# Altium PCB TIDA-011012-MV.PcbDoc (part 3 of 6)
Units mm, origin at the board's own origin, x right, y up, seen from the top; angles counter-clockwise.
Board outline 360 x 280 mm, 4 copper layers (Top Layer, Layer 1, Layer 2, Bottom Layer), stack 2.066 mm thick; 566 components, 345 nets, 1738 pads, 2486 vias.
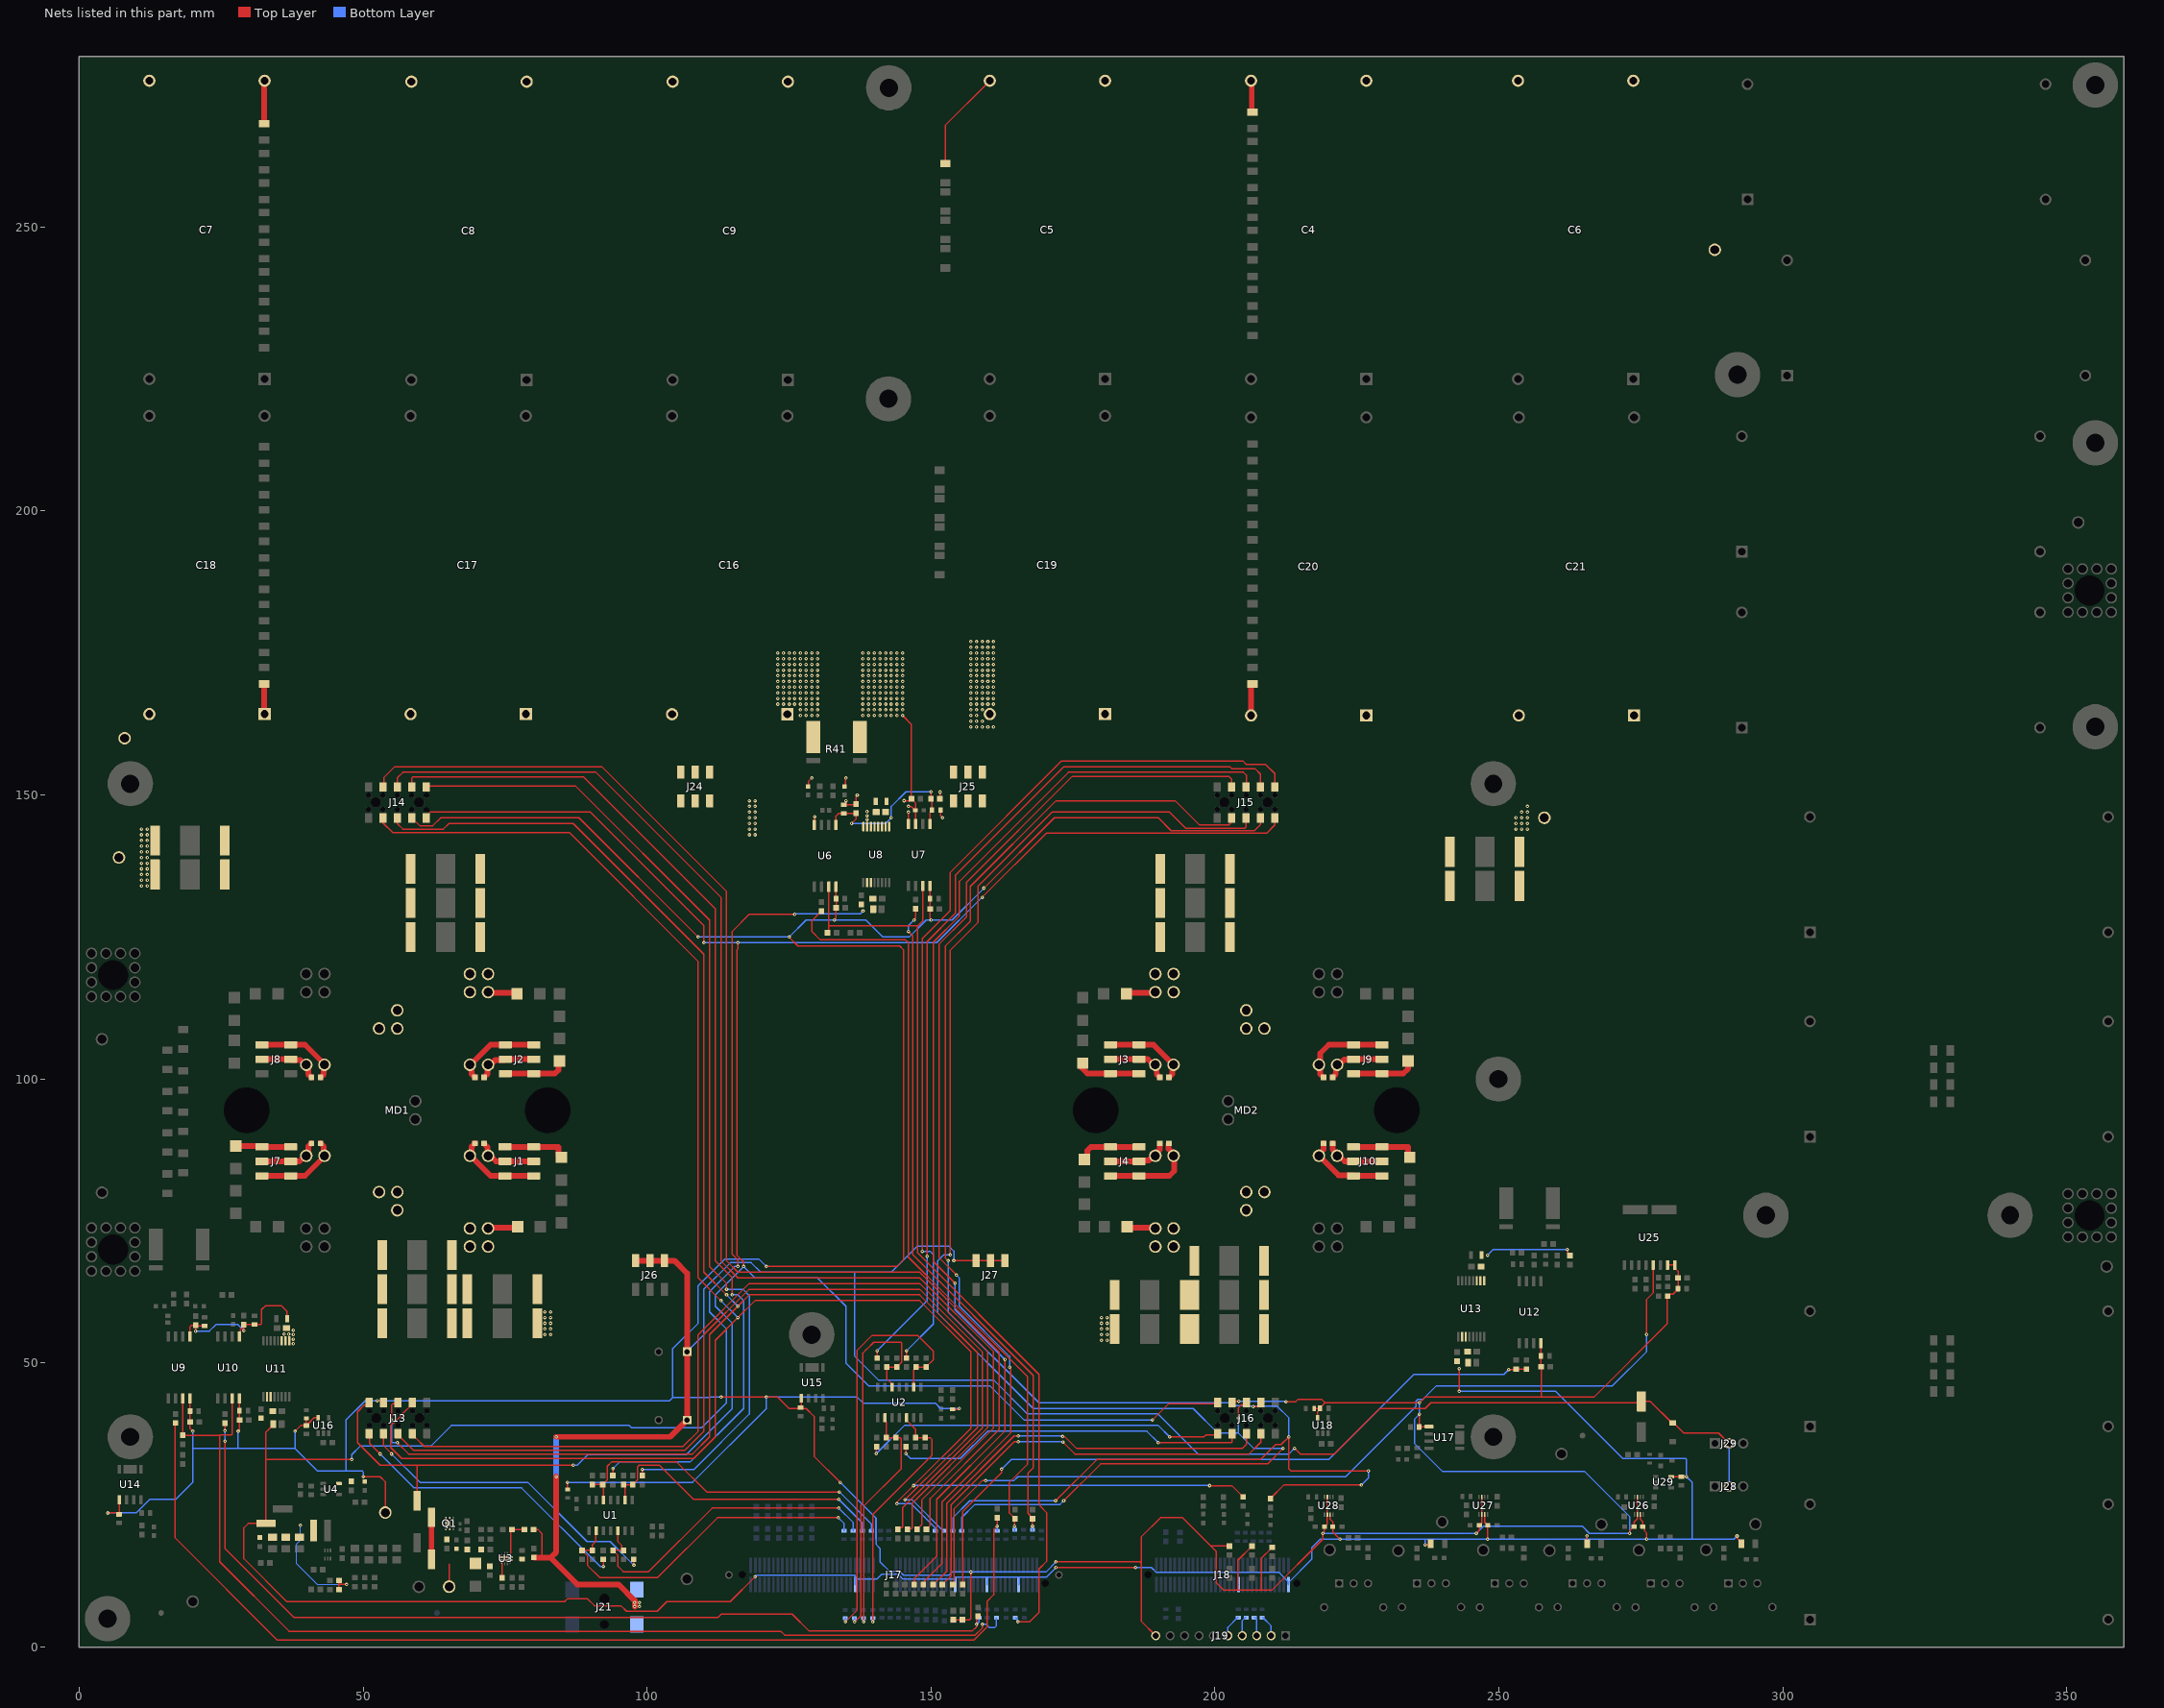
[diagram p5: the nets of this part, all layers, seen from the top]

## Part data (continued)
R142: library part CMP-0022816-5, "RES, 15.0 k, 1%, 0.1 W, 0603", Manufacturer=Yageo, Power_W=100mW, Supplier Part Number 1=311-15.0KHRCT-ND, TempCo="100 ppm/C", Tolerance_%=1%, Value2=0.1W, Value_Code=15k0, ValueDisplayed=15.0k
R144: library part CMP-0022917-4, "RES, 220 k, 1%, 0.1 W, 0603", Manufacturer=Yageo, Power_W=100mW, Supplier Part Number 1=311-220KHRCT-ND, TempCo="100 ppm/C", Tolerance_%=1%, Value2=0.1W, Value_Code=220k
R145: library part CMP-0023404-3, "RES, 10.0 k, 0.1%, 0.1 W, 0603", Manufacturer="Susumu Co Ltd", Power_W=100mW, Supplier Part Number 1=RG16P10.0KBCT-ND, TempCo="25 ppm/C", Tolerance_%=0.1%, Value2=0.1W, Value_Code=10k0, ValueDisplayed=10.0k
R146: library part CMP-0023020-5, "RES, 30.0 k, 1%, 0.1 W, 0603", Manufacturer=Yageo, Power_W=100mW, Supplier Part Number 1=311-30.0KHRCT-ND, TempCo="100 ppm/C", Tolerance_%=1%, Value2=0.1W, Value_Code=30k0, ValueDisplayed=30.0k
R151 R152 R166 R167 R181 R182: library part CMP-0025687-2, "RES, 10.0, 0.1%, 0.1 W, 0603", Manufacturer=Vishay-Dale, Power_W=100mW, Supplier Part Number 1=TNP10.0AACT-ND, TempCo="25 ppm/C", Tolerance_%=0.1%, Value2=0.1W, Value_Code=10R0, ValueDisplayed=10.0
R153 R163 R168 R178 R183: library part CMP-0023099-5, "RES, 40.2, 1%, 0.1 W, 0603", Manufacturer=Yageo, Power_W=100mW, Supplier Part Number 1=311-40.2HRCT-ND, TempCo="100 ppm/C", Tolerance_%=1%, Value2=0.1W, Value_Code=40R2, ValueDisplayed=40.2
R154 R169: library part CMP-0022736-4, "RES, 100, 1%, 0.1 W, 0603", Manufacturer=Yageo, Power_W=100mW, Supplier Part Number 1=311-100HRCT-ND, TempCo="100 ppm/C", Tolerance_%=1%, Value2=0.1W, Value_Code=100R, ValueDisplayed=100
R155 R156 R157 R158 R159 R160 R161 R162 R170 R171 R172 R173 R174 R175 R176 R177: library part CMP-0120473-1, "Thick Film High Voltage Chip Resistors 1206 1.5MOhm ±1% ±100ppm/°C", Manufacturer=Bourns, Operating Temperature Range="-55°C to +155°C", Power_W=250mW, TempCo=100ppm/°C, Tolerance_%=1%
R164 R179: library part CMP-0023153-5, "RES, 4.70 k, 1%, 0.1 W, 0603", Manufacturer=Yageo, Power_W=100mW, Supplier Part Number 1=311-4.70KHRCT-ND, TempCo="100 ppm/C", Tolerance_%=1%, Value2=0.1W, Value_Code=4k70, ValueDisplayed=4.70k
R165 R180 R185: library part CMP-0025892-5, "RES, 18 k, 5%, 0.1 W, 0603", Manufacturer=Yageo, Power_W=100mW, Supplier Part Number 1=311-18KGRCT-ND, TempCo="100 ppm/C", Tolerance_%=5%, Value2=0.1W, Value_Code=18k0, ValueDisplayed=18k
R184: library part CMP-0022680-4, "RES, 1.00 k, 1%, 0.1 W, 0603", Manufacturer=Panasonic, Power_W=100mW, Supplier Part Number 1=P1.00KHCT-ND, TempCo="100 ppm/C", Tolerance_%=1%, Value2=0.1W, Value_Code=1k00, ValueDisplayed=1.00k
R187: library part CMP-0023921-2, "RES, 200, 0.1%, 0.1 W, 0603", Manufacturer="Yageo America", Power_W=100mW, TempCo="25 ppm/C", Tolerance_%=0.1%, Value2=0.1W, Value_Code=200R, ValueDisplayed=200
R188: library part CMP-0098286-1, "10 kOhms ±5% 0.1W, 1/10W Chip Resistor 0603 (1608 Metric) Thick Film", Digikey Part Number=541-CRCW060310K0JNEBCCT-ND, Manufacturer=Vishay, Mouser Part Number=71-CRCW060310K0JNEBC, Operating Temperature Range="-55°C to +155°C", Power_W=100mW, TempCo=200ppm/°C, Tolerance_%=5%
R190 R192: library part CMP-0023235-5, "RES, 680, 1%, 0.1 W, 0603", Manufacturer=Yageo, Power_W=100mW, Supplier Part Number 1=311-680HRCT-ND, TempCo="100 ppm/C", Tolerance_%=1%, Value2=0.1W, Value_Code=680R, ValueDisplayed=680
R193 R196 R208: library part CMP-0023069-5, "RES, 390, 1%, 0.1 W, 0603", Manufacturer=Yageo, Power_W=100mW, Supplier Part Number 1=311-390HRCT-ND, TempCo="100 ppm/C", Tolerance_%=1%, Value2=0.1W, Value_Code=390R, ValueDisplayed=390
R194 R197 R209: library part CMP-0022769-5, "RES, 120, 1%, 0.1 W, 0603", Manufacturer=Yageo, Power_W=100mW, Supplier Part Number 1=311-120HRCT-ND, TempCo="100 ppm/C", Tolerance_%=1%, Value2=0.1W, Value_Code=120R, ValueDisplayed=120
R195 R198 R210: library part CMP-0025815-4, "RES, 47, 5%, 0.1 W, AEC-Q200 Grade 0, 0603", Manufacturer=Vishay-Dale, Power_W=100mW, Supplier Part Number 1=541-47GCT-ND, TempCo="200 ppm/C", Tolerance_%=5%, Value2=0.1W, Value_Code=47R0, ValueDisplayed=47
R199: library part CMP-0022553-4, "RES, 68.1, 1%, 0.1 W, AEC-Q200 Grade 0, 0603", Manufacturer=Vishay-Dale, Power_W=100mW, Supplier Part Number 1=541-68.1HCT-ND, TempCo="100 ppm/C", Tolerance_%=1%, Value2=0.1W, Value_Code=68R1, ValueDisplayed=68.1
R200 R201 R206 R207 R211 R212 R213 R214: library part CMP-0018693-3, "RES, 4.7, 5%, 0.25 W, AEC-Q200 Grade 0, 1206", Manufacturer=Vishay-Dale, Power_W=250mW, Supplier Part Number 1=541-4.7ECT-ND, TempCo="200 ppm/C", Tolerance_%=5%, Value2=0.25W, Value_Code=4R70, ValueDisplayed=4.7
R202: library part CMP-0025942-5, "RES, 8.2 k, 5%, 0.1 W, 0603", Manufacturer=Yageo, Power_W=100mW, Supplier Part Number 1=311-8.2KGRCT-ND, TempCo="100 ppm/C", Tolerance_%=5%, Value2=0.1W, Value_Code=8k20, ValueDisplayed=8.2k
R203: library part CMP-0025894-5, "RES, 1.2 k, 5%, 0.1 W, 0603", Manufacturer=Yageo, Power_W=100mW, Supplier Part Number 1=311-1.2KGRCT-ND, TempCo="100 ppm/C", Tolerance_%=5%, Value2=0.1W, Value_Code=1k20, ValueDisplayed=1.2k
TP1 TP3 TP13 TP14: library part CMP-0055147-2, "Test Point, Multipurpose, Red, TH", Color=Red, Manufacturer="Keystone Electronics", Supplier Part Number 1=36-5010-ND
TP2 TP17 TP18 TP21 TP22 TP23: library part CMP-0055148-2, "Test Point, Multipurpose, Black, TH", Color=Black, Manufacturer="Keystone Electronics", Supplier Part Number 1=36-5011-ND
TP4 TP5 TP6 TP7 TP8 TP9 TP10 TP11 TP12 TP15 TP16 TP19 TP20: library part CMP-0055155-2, "Test Point, Compact, Blue, TH", Color=Blue, Manufacturer="Keystone Electronics", Supplier Part Number 1=36-5122-ND
U1 U2: library part CMP-0093039-1, "Schmitt-trigger inputs quadruple bus buffer gates with 3-state outputs 14-SOIC -40 to 125", Manufacturer="Texas Instruments", Max Supply Voltage=6V, Min Supply Voltage=2V, Mouser Part Number=595-SN74HCS126DR, Nominal Supply Current=0.1uA, Operating Temperature Range="-40°C to +125°C"
U3: library part CMP-0088329-1, "2.7- 23V, 5.5 A, 28 mΩ Reverse Current Blocking eFuse with Input Reverse Polarity Protection", Manufacturer="Texas Instruments", Max Supply Voltage=23V, Min Supply Voltage=2.7V, Nominal Supply Current=0.5-6A, Operating Temperature Range="-40°C to +125°C", Output Voltage=42V, Threshold Voltage=1.2/1.1V
U4: library part CMP-0074640-3, "500-mA, Low IQ, Small Size, Low Dropout Regulator, DBV0005A (SOT-23-5)", Alternate Manufacturer="Texas Instruments"
U5: library part CMP-0047826-1, "4.2-V to 17-V Input, 3-A Synchronous Buck Converter in SOT563", Manufacturer="Texas Instruments", Max Supply Voltage=17V, Min Supply Voltage=4.2V, Nominal Supply Current=110uA, Operating Temperature Range="-40°C to +125°C", Output Voltage=0.6-7V, Switching Frequency=600kHz
U6 U9: library part CMP-0125127-1, "Automotive, Precision, ±250-mV Input Isolated Delta-Sigma Modulators With External Clock", Manufacturer="Texas Instruments", Max Supply Voltage=5.5V, Min Supply Voltage=2.7V, Operating Temperature Range="-40°C to +125°C"
U7 U10: library part CMP-0860008-1, "AMC1336 Small, High-Precision, Reinforced Isolated Delta-Sigma Modulator With Input Optimized for Voltage Sensing Applications, DWV0008A (SOIC-8)", Alternate Manufacturer="Texas Instruments", Alternate PartNumber=AMC1336DWV
U8 U11 U13: library part CMP-0123146-1, "Ultra-Small, 1.5W, 5.0V, 5kVRMS Isolation, Industrial DC/DC Module", Manufacturer="Texas Instruments", Max Supply Voltage=5.5V, Min Supply Voltage=4.5V, Nominal Supply Current=7-545mA, Operating Temperature Range="-40°C to +125°C", Output Voltage=5/5.5V, Switching Frequency=76MHz
U12: library part CMP-0092444-3, "Dual, Fast Response, Reinforced Isolated Window Comparator with Adjustable Threshold", Manufacturer="Texas Instruments", Operating Temperature Range=to
U14 U15 U17: library part CMP-0122473-1, "Automotive ±1.5°C, 3-kVRMS Isolated Temperature Sensor With Analog Output With < 2 Seconds Response Time and 500VRMS Working Voltage", Manufacturer="Texas Instruments", Max Supply Voltage=5.5V, Min Supply Voltage=2.3V, Operating Supply Current=10uA, Operating Temperature Range="-40°C to +150°C"
U16 U18: library part CMP-0081550-1, "Low-Power, Rail-to-Rail In and Out, 1-MHz Operational Amplifier, DBV0005A (SOT-23-5)", Alternate Manufacturer="Texas Instruments", Alternate PartNumber=TLV9001IDBVT
U19 U21 U23: library part CMP-0092228-1, "Fiber Optic Transmitter 650nm 1.8V TOSLINK", Digikey Part Number=TOTX1350(F)-ND, Forward Current=6mA, Manufacturer=Toshiba, Max Supply Voltage=5.25V, Min Supply Voltage=4.75V, Mouser Part Number=757-TOTX1350F, Operating Temperature Range="-40°C to +85°C"
U20 U22 U24: library part CMP-0092227-1, "Fiber Optic Receiver General Purpose 10Mbps -27dBm 4.75V ~ 5.25V", Digikey Part Number=TORX1350A(F)-ND, Manufacturer=Toshiba, Max Supply Voltage=5.25V, Min Supply Voltage=4.75V, Mouser Part Number=757-TORX1350AF, Operating Temperature Range="-40°C to +85°C"
U25: library part CMP-0097984-1, Manufacturer="Texas Instruments", Operating Temperature Range=to
U26 U27 U28: library part CMP-0093827-1, "Single-Bit Fixed Direction Voltage-Level Translator with Schmitt-Trigger Inputs and 3-State Outputs", Manufacturer="Texas Instruments", Operating Temperature Range="-40°C to +125°C"
U29: library part CMP-0051712-2, "Single Power Supply BUFFER Logic Level Shifter (no enable), DBV0005A, LARGE T&R", Alternate Manufacturer="Texas Instruments", F @ Nom Voltage(Max)(Mhz)=50, Generic Part Number=SN74LV1T34, ICC @ Nom Voltage(Max)(mA)=0.01, Operating Temperature Range(C)="-40 to 125", Rating=Catalog, tpd @ Nom Voltage(Max)(ns)=14.5,9.5,8.0,6.5, Voltage(Nom)(V)=1.8,2.5,3.3,5.5
ZZ1: library part CMP-0003616-3
ZZ2: library part CMP-0077236-1
ZZ3: library part CMP-0077237-1
ZZ4: library part CMP-0077238-1

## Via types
v1: diameter 0.6, hole 0.2, Top Layer to Bottom Layer, tented both sides, 2486 vias

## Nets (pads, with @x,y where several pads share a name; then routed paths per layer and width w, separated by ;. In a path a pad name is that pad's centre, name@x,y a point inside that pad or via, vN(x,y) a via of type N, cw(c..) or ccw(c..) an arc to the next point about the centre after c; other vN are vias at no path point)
3V3: C66.1 C73.1 C74.1 C82.1 C83.1 C92.1 C93.1 C101.1 C102.1 C113.1 C114.1 C123.1 C126.1 C129.1 C130.1 C133.1 C141.2 C143.2 C145.2 C158.2 C159.1 D32.2 J13.3 J14.3 J15.3 J16.3 J19.10 R45.2 R46.2 R47.2 R64.1 R104.1 R149.2 R150.2 R202.1 R218.2 R219.2 TP3.1 U4.5 U6.8 U7.8 U9.8 U10.8 U12.8 U14.1 U15.1 U16.5 U17.1 U18.5 U25.9 U25.10 U26.3 U26.6 U27.3 U27.6 U28.3 U28.6 | length 1015.7
  Top Layer w0.254: v1(5.005,23.602) 6.76,23.602 C123.1@7.005,23.357 7.08,23.431 U14.1@7.08,25.916 ; U9.8@19.505,43.75 19.505,38.495 v1(20,38) ; v1(28,38) 28.23,38.23 C102.1@28.23,39.949 28.205,39.974 U10.8@28.205,43.75 ; v1(38,38) 39,39 40.105,39 40.373,39.268 40.373,39.373 41.375,40.375 U16.5@42.05,40.375 ; C129.1@40,39 R218.2@40,40.275 ; v1(50,30) 53,30 53.895,29.105 TP3.1@53.895,23.678 ; v1(52.473,43.363) 53.267,43.363 J13.3@53.61,43.02 ; J14.3@58.59,145.975 59.972,144.593 62.271,144.593 63.677,146 88,146 v1(109,125) ; R64.1@86,27.725 v1(86,29) ; v1(113,44) v1(121,44) 123,44 125,42 126.547,42 126.783,42.236 127.019,42 128,42 129.4,40.6 129.4,33.6 v1(134,29) ; v1(121,67) 144,67 145.143,68.143 145.143,122.773 144.473,123.443 126.557,123.443 v1(125,125) ; C126.1@126.883,42.236 127.151,42.504 U15.1@127.151,44.241 ; v1(133,128) 133,128.067 133.244,128.31 133.244,130.092 C74.1@133.294,130.142 133.289,130.147 C73.1@133.289,131.764 133.28,131.774 133.28,133.854 U6.8@133.271,133.863 ; U7.8@149.806,134.013 149.823,133.995 149.823,131.782 C82.1@149.841,131.764 149.841,129.938 C83.1@149.846,129.933 149.846,128.154 v1(150,128) ; R104.1@153.763,41.85 154.85,41.85 v1(155,42) ; R149.2@153.922,4.821 R150.2@155.522,4.821 155.55,4.793 156.77,4.793 157,5.023 v1(157,13.2) ; v1(159.315,133.615) 171.7,146 190,146 192.269,143.731 206.931,143.731 207.99,144.79 J15.3@207.99,146.18 ; v1(172,15) 186.739,15 ; 186.979,15.005 186.975,15 186.739,15 ; J19.10@189.57,2 187,4.57 187,14.739 ; R47.2@202.541,17.794 199.252,17.794 ; J16.3@203.01,42.82 203.478,43.288 v1(204.183,43.288) ; R46.2@206.502,17.794 206.502,17.769 204,15.267 204,10.149 204.149,10 ; R45.2@210.07,17.558 210.07,17.533 208.14,15.603 208.14,10 ; v1(212.491,43.201) 214.209,43.201 214.635,43.627 218.758,43.627 219.385,43 ; R219.2@217.45,42 C133.1@218.49,42 ; U18.5@218.05,40.375 218.05,41.455 218.49,41.895 C133.1@218.49,42 ; C145.2@219.28,21.22 219.28,20.346 219,20.067 v1(219,20) 219,19 210,10 208.14,10 ; C145.2@219.343,21.22 219.769,21.646 U28.6@219.769,23.319 U28.3@219.769,26.419 ; v1(236,41) 236,38.828 C130.1@235.927,38.755 235.99,38.818 U17.1@237.683,38.818 ; v1(246,20) 246.543,20.543 C143.2@246.543,21.475 ; C143.2@246.606,21.475 246.981,21.849 U27.6@246.981,23.345 U27.3@246.981,26.445 ; U12.8@257.37,53.5 C113.1@257.37,51.228 257.37,49.435 C114.1@257.424,49.38 257.424,44.038 257.463,44 ; v1(273,20) 273,20.492 273.719,21.21 C141.2@273.782,21.21 273.782,21.994 274.381,22.593 U26.6@274.381,23.345 U26.3@274.381,26.445 ; U25.9@279.675,67.247 U25.10@280.945,67.247 280.945,66.722 281.532,66.135 C158.2@281.532,63.125 281.532,63.02 280.635,62.123 280.043,62.123 279.649,61.729 279.649,56.949 266.7,44 257.463,44 ; 186.739,15 187,14.739 ; 187,14.739 187,19.366 190.434,22.8 194.246,22.8 199.252,17.794 ; 199.252,17.794 200.2,16.846 200.2,11.354 201.554,10 204.149,10 ; 204.149,10 208.14,10 ; C133.1@218.49,42 218.49,42.105 219.385,43 ; 219.385,43 v1(236,43) 237,44 257.463,44
  Bottom Layer w0.253: 140.301,18.084 140.301,18.963
  Bottom Layer w0.254: v1(5.005,23.602) 10.038,23.602 12.437,26 17,26 20,29 20,34.969 ; v1(20,38) 20,34.969 ; v1(28,38) 28,35.106 27.863,34.969 ; 37.969,34.969 27.863,34.969 ; v1(38,38) 38,34.969 41.969,31 46.985,31 ; v1(50,30) 50,30.851 49.851,31 46.985,31 ; v1(86,29) 108,29 121,42 v1(121,44) 137,44 138.044,42.956 150.732,42.956 151.688,42 v1(155,42) ; 104.5,44 104.5,52.5 109,57 109,63.642 113.615,68.257 119.743,68.257 v1(121,67) ; v1(109,125) v1(125,125) 128,128 v1(133,128) 138.524,128 141.524,125 146.136,125 149.136,128 v1(150,128) 153.7,128 v1(159.315,133.615) ; v1(113,44) 111,44 110.9,43.9 104.5,43.9 103.963,43.363 v1(52.473,43.363) 50.363,43.363 47,40 47,31.015 46.985,31 ; v1(134,29) 140.3,22.7 140.3,18.964 ; 140.301,18.083 141,17.384 141,15 142.657,13.343 144.457,13.343 145.163,12.637 153.137,12.637 153.7,13.2 v1(157,13.2) 157.018,13.218 170.218,13.218 v1(172,15) ; v1(204.183,43.288) 204.227,43.245 212.447,43.245 v1(212.491,43.201) ; v1(219,20) v1(246,20) 247.262,21.262 264.667,21.262 265.93,20 v1(273,20) 273,23 265.105,30.895 240.068,30.895 235.174,35.789 235.174,40.174 v1(236,41) v1(236,43) ; 20,34.969 27.863,34.969
5V: C63.1 C67.1 C68.1 C69.1 C88.2 C90.1 C107.2 C109.1 C119.2 C121.1 C137.2 C142.2 C144.2 C146.1 D31.2 J17.48 J17.84 J17.98 J17.112 J18.158 J18.180 J23.1 L1.1 L2.1 L3.1 L7.2 R144.2 R165.2 R180.2 R185.2 U8.2 U8.3 U11.2 U11.3 U13.2 U13.3 U26.7 U27.7 U28.7 U29.5 | length 617.5
  Top Layer w0.254: C107.2@34.191,39.284 34.191,39.133 32.892,37.834 32.892,32.972 ; v1@38.781,21.358 38.889,21.358 v1(38.943,21.412) ; R144.2@45.743,10.123 45.743,10.902 ; C63.1@45.743,11.748 45.743,10.902 ; v1(47.065,11.023) 45.865,11.023 45.743,10.902 ; v1(48,33) 32.92,33 32.892,32.972 ; v1(116,67) 116,68.141 115,69.141 115,126 118,129 v1(126,129) ; v1(119,12.359) 114.641,8 103.487,8 101.783,6.296 96.377,6.296 95.415,7.257 90.743,7.257 89.534,8.466 85.942,8.466 85.476,8 36.548,8 29,15.548 29,21 29.761,21.761 J23.1@32.892,21.761 32.892,32.972 ; v1(172,14) v1(186,14) ; U28.7@220.269,23.319 220.269,22.51 220.723,22.056 C137.2@220.723,21.215 C137.2@220.723,21.215 220.724,20.276 v1(222,19) ; v1(237,18) 237.807,18 L3.1@237.966,18.159 ; v1(243,45) v1(243,49) ; U27.7@247.481,23.345 247.481,21.954 247.96,21.475 C144.2@248.024,21.475 248,21.451 v1(248,19) ; v1(265.49,19.553) 265.49,18.192 L2.1@265.52,18.162 ; U26.7@274.881,23.345 274.881,22.517 275.32,22.078 C142.2@275.32,21.219 275.356,21.219 275.61,20.965 275.61,20.457 276,20.067 v1(276,19) ; U29.5@280.342,29.969 282.128,29.969 C146.1@282.138,29.96 282.178,30 v1(283,30) ; v1(291.919,19.538) 291.966,19.491 291.966,19.104 292.658,18.412 L1.1@292.658,18.162
  Bottom Layer w0.2: v1(38.943,21.412) 38.943,18.856 38.245,18.158 38.245,14.655 41.877,11.023 v1(47.065,11.023)
  Bottom Layer w0.254: v1(48,33) 48,33.887 49.486,35.373 61.912,35.373 65.539,39 96.873,39 97.28,38.593 109.593,38.593 114,43 114,56 111,59 111,62.576 115.424,67 v1(116,67) ; v1(119,12.359) 119.002,12.359 119.272,12.629 136.61,12.629 136.647,12.593 J17.48@136.647,12 ; v1(126,129) 126.094,129 126.182,129.089 137.536,129.089 138.016,129.568 v1(138.019,129.568) ; J17.48@136.647,10.994 J17.48@136.647,12 ; J17.84@154.247,10.994 J17.84@154.247,12 ; J17.98@159.847,10.994 J17.98@159.847,12.3 ; J17.112@165.447,10.994 165.524,11.072 J17.112@165.524,12.3 ; v1(172,14) 170.3,12.3 J17.112@165.524,12.3 ; v1(186,14) 188.797,14 189.667,13.13 204.055,13.13 ; J18.158@204.115,10.994 204.055,11.054 204.055,13.13 ; v1(237,18) 237,18.955 236.955,19 ; v1(243,45) 260,45 271.8,33.2 282.851,33.2 283,33.051 v1(283,30) 284,29 284,19.12 284.12,19 ; v1(265.49,19.553) 265.49,19.003 265.494,19 ; v1(276,19) 266.043,19 265.494,19 ; v1@276.038,19 284.12,19 ; v1(291.919,19.538) 291.382,19 284.12,19 ; J17.48@136.647,12 140.5,12 141.306,12.806 144.194,12.806 145,12 J17.84@154.247,12 ; J17.84@154.247,12 154.247,12.151 154.396,12.3 J17.98@159.847,12.3 ; J17.98@159.847,12.3 J17.112@165.524,12.3 ; 204.055,13.13 211.291,13.13 212.792,11.63 212.792,11.117 J18.180@212.915,10.994 212.915,11.344 217,15.429 217,17.464 218.536,19 v1(222,19) 236.955,19 ; 236.955,19 247.436,19 v1(248,19) 265.494,19
5V_ISO_AC_SENS: C94.1 C95.1 C103.1 C104.1 C108.2 C110.1 U9.1 U10.1 U11.9 U11.10 U11.11 | length 30.6
  Top Layer w0.254: U9.1@19.505,54.65 19.505,56.405 19.7,56.6 20.406,56.6 C95.1@20.461,56.545 ; v1(20.5,55.6) 20.5,56.506 C95.1@20.461,56.545 ; C94.1@22.1,56.545 C95.1@20.461,56.545 ; U10.1@28.205,54.65 28.378,54.823 28.378,55.851 28.527,56 28.751,56 28.751,56.517 C104.1@28.866,56.632 ; v1(29,55.7) 29,56.497 C104.1@28.866,56.632 ; C108.2@36.625,57.812 36.625,59.075 35.6,60.1 32.8,60.1 32.1,59.4 32.1,56.94 31.951,56.791 C103.1@30.86,56.791 29.025,56.791 C104.1@28.98,56.746 C104.1@28.866,56.632
  Bottom Layer w0.254: v1(20.5,55.6) 20.532,55.632 22.932,55.632 24.1,56.8 27.9,56.8 v1(29,55.7)
  other v1: 37.7,53.4 37.7,54.2 37.7,55 36.1,55.1 36.9,55.1 37.7,55.8
5V_ISO_DC_SENS: C75.1 C76.1 C84.1 C85.1 C89.2 C91.1 U6.1 U7.1 U8.9 U8.10 U8.11 | length 30.8
  Top Layer w0.254: U6.1@133.271,144.763 133.271,146.311 133.738,146.778 C75.1@134.655,146.778 136.761,146.778 C76.1@136.816,146.833 136.816,145.816 v1(136,145) ; U7.1@149.806,144.913 149.806,146.902 150.15,147.246 C84.1@150.15,147.351 150.15,149.184 149.969,149.365 v1(149.969,150.575)
  Bottom Layer w0.254: v1(136,145) 142,145 v1(143,146) 143,148 145.575,150.575 v1(149.969,150.575)
5V_ISO_SN_SENS: C118.2 C120.1 R181.1 U13.9 U13.10 U13.11 | length 15.7
  Top Layer w0.254: v1(262,70) 262.152,69.848 262.152,69.27 R181.1@262.5,68.922
  Bottom Layer w0.254: v1(248,69) 249,70 v1(262,70)
12V: J13.1 J14.1 J15.1 J16.1 J20.2 | length 444.8
  Top Layer w0.254: J13.1@51.07,42.82 50.853,42.603 50.203,42.603 49,41.4 49,36 53,32 59.527,32 ; J20.2@59.491,25.762 59.491,31.963 59.527,32 ; J14.1@61.13,146.18 61.638,146.688 61.638,146.79 61.89,147.041 89.959,147.041 110,127 v1(110,124) ; v1(87,32) 59.527,32 ; v1(116,124) 116,122.916 115.857,122.773 115.857,68.927 117,67.784 v1(117,67) ; v1(159,132) 170.277,143.277 209.077,143.277 210.53,144.73 J15.1@210.53,146.18 ; v1(189,40) 191.82,42.82 J16.1@200.47,42.82
  Bottom Layer w0.254: v1(87,32) 87.687,32 89.533,33.845 106.845,33.845 115,42 115,57 112,60 112,62 v1(117,67) 119,65 130,65 135,60 135,50 139,46 160.358,46 166.358,40 v1(189,40) ; v1(110,124) 151,124 v1(159,132)
12V_FET_DRAIN: Q1.1 Q1.2 Q1.5 Q1.6 Q1.8 R140.1
12V_IN: C10.1 C55.1 C56.1 C57.1 C122.1 D33.1 J21.1 J21.1A J26.1 J26.3 J26.5 J27.1 J27.3 J27.5 J28.2 J29.2 R134.2 U3.5 | length 372.9
  Top Layer w0.254: U3.5@75.16,15.824 U3.5@75.183,15.847 ; C10.1@77.972,15.518 C10.1@78,15.49 ; R134.2@80.014,20.703 80.764,20.703 81.497,19.971 81.497,15.787 81.561,15.723 ; v1(154,68) 156,68 156.025,68.025 J27.1@157.96,68.025 J27.3@160.5,68.025 J27.5@163.04,68.025 ; v1(214,35) 215,34 221,34 229,42 237,42 238,43 274.849,43 C122.1@275.075,43.226 276.668,43.226 280.452,39.443 D33.1@280.604,39.443 280.757,39.443 282.511,37.688 288.662,37.688 J29.2@290.5,35.85
  Top Layer w1: C57.1@80.071,15.774 80.123,15.723 81.561,15.723 83,15.723 ; v1(84,30) 84,16.723 83,15.723 ; v1(84,37) 104.071,37 C56.1@107.037,39.966 C55.1@107.037,51.989 107.037,65.794 104.805,68.025 J26.5@103.04,68.025 J26.3@100.5,68.025 J26.1@97.96,68.025 ; v1(97.821,7.123) v1(97.821,7.839) 97.821,8.179 95,11 87.723,11 83,15.723
  Bottom Layer w0.254: C55.1@107.037,51.989 110,54.952 110,63 114.677,67.677 118.323,67.677 120,66 136.621,66 ; v1(154,68) 154,68.744 154.012,68.755 154.012,69.688 153.1,70.6 147.6,70.6 143,66 136.621,66 ; v1(214,35) 213,34 197,34 189.976,41.024 166.976,41.024 161,47 140.745,47 136.562,51.182 136.562,65.941 136.621,66 ; J28.2@290.5,28.295 J29.2@290.5,35.85
  Bottom Layer w1: v1(84,30) v1(84,37)
  other v1: 98.666,7.123 98.666,7.839
12V_OUT: C59.1 D29.2 D30.1 J20.1 J22.1 R135.2 R139.2 TP1.1 U3.6 | length 11.4
  Top Layer w0.254: TP1.1@65.146,10.623 65.146,14.63
  Top Layer w1: J22.1@62.031,15.426 J20.1@62.031,22.841
AC_BUF_PMW1: J13.2 R75.2 | length 52.9
  Top Layer w0.254: J13.2@51.07,37.38 51.167,37.283 51.167,35.833 v1(53,34) ; v1(92.276,14.192) R75.2@92.276,15.434
  Bottom Layer w0.254: v1(53,34) 59,28 77.9,28 91.708,14.192 v1(92.276,14.192)
AC_BUF_PMW2: J13.4 R76.2 | length 55.8
  Top Layer w0.254: J13.4@53.61,37.38 53.61,35.457 55,34.067 v1(55,34) ; R76.2@97.63,15.434 97.63,14.615 97.684,14.561 v1(97.684,14.394)
  Bottom Layer w0.254: v1(55,34) 60,29 79,29 89.419,18.581 93.497,18.581 v1(97.684,14.394)
AC_BUF_PMW3: J14.2 R80.2 | length 175.2
  Top Layer w0.254: J14.2@61.13,151.62 87.38,151.62 111,128 111,67 114,64 v1(114,63) ; R80.2@99.141,30.184 v1(99.141,31.285)
  Bottom Layer w0.254: v1(99.141,31.285) 108.285,31.285 118,41 118,61.881 116.881,63 v1(114,63)
AC_BUF_PMW4: J14.4 R84.2 | length 183.8
  Top Layer w0.254: J14.4@58.59,151.62 J14.4@58.687,151.717 ; J14.4@58.59,151.717 58.59,153.041 58.739,153.19 88.81,153.19 112,130 112,68 115,65 v1(115,62) ; R84.2@93.964,30.184 v1(93.964,31.386)
  Bottom Layer w0.254: v1(93.964,31.386) 95.151,32.573 107.573,32.573 117,42 117,61 116,62 v1(115,62)
AC_DS1: D9.2 J1.1 J1.2 | length 11.4
  Top Layer w0.5: J1.2@75,88 J1.2@75.007,88.007
  Top Layer w1: J1.2@74.975,88.04 J1.1@80.025,88.04 84.36,88.04 84.4,88 84.4,86.5 D9.2@84.7,86.2
AC_DS2: D21.2 J7.1 J7.2 | length 9.7
  Top Layer w1: D21.2@27.605,88.225 30.105,88.225 30.155,88.175 32.04,88.175 J7.2@32.175,88.04 J7.1@37.225,88.04
AC_DS3: D10.2 J2.1 J2.2 | length 11
  Top Layer w1: J2.1@75.025,100.96 J2.2@80.075,100.96 83.76,100.96 84.4,101.6 D10.2@84.4,103
AC_FAULT_FET1: J13.6 R97.1 | length 167.9
  Top Layer w0.254: J13.6@56.15,37.38 56.658,36.872 56.658,36.848 58.906,34.6 106.6,34.6 110,38 110,55 118,63 148,63 159,52 159,38.53 145,24.53 145,21.2 144.834,21.034 144.5,21.034 R97.1@144.164,20.698
AC_FAULT_FET2: J13.8 R110.1 | length 166.5
  Top Layer w0.254: J13.8@58.69,37.38 58.69,37.375 59.198,36.867 59.203,36.867 60.77,35.3 106.3,35.3 109,38 109,55 118,64 148,64 160,52 160,38.64 146.706,25.346 146.706,21.006 146.543,20.843 145.981,20.843 R110.1@145.836,20.698
AC_FAULT_FET3: J14.6 R113.1 | length 223.4
  Top Layer w0.254: J14.6@56.05,151.62 56.05,153.051 56.999,154 91,154 113,132 113,68 116,65 148,65 161,52 161,38.545 148.4,25.945 148.4,21.615 147.508,20.723 R113.1@147.508,20.698
AC_FAULT_FET4: J14.8 R124.1 | length 228
  Top Layer w0.254: J14.8@53.51,151.62 53.625,151.735 53.625,153.051 55.574,155 92,155 114,133 114,68 116,66 148,66 152.636,61.364 152.636,61.307 162,51.942 162,38.302 149.845,26.147 149.845,21.388 149.18,20.723 R124.1@149.18,20.698
AC_G1: J1.5 J1.6 MD1.G1 R17.1 | length 15
  Top Layer w1: MD1.G1@68.9,86.5 69.13,86.73 69.13,88.13 R17.1@69.7,88.7 ; MD1.G1@69,86.4 72.44,82.96 J1.6@74.975,82.96 J1.5@80.025,82.96
AC_G2: J7.5 J7.6 MD1.G2 R26.1 | length 15.1
  Top Layer w1: J7.6@32.175,82.96 J7.5@37.225,82.96 39.76,82.96 43.3,86.5 43.07,86.73 43.07,88.13 R26.1@42.5,88.7
AC_G3: J2.5 J2.6 MD1.G3 R18.1 | length 15
  Top Layer w1: MD1.G3@69,102.5 69,102.6 72.44,106.04 J2.5@75.025,106.04 J2.6@80.075,106.04 ; MD1.G3@69.13,102.5 69.13,100.87 R18.1@69.7,100.3
AC_G4: J8.5 J8.6 MD1.G4 R27.1 | length 15.1
  Top Layer w1: J8.5@32.175,106.04 J8.6@37.225,106.04 39.76,106.04 43.3,102.5 43.07,102.27 43.07,100.87 R27.1@42.5,100.3
AC_GD_RDY: J13.7 J14.7 R52.2 R79.1 | length 370.7
  Top Layer w0.254: J14.7@53.625,146.295 53.51,146.18 53.51,145.09 55.196,143.404 86.296,143.404 109,120.7 109,65 v1(113,61) ; J13.7@58.69,42.82 J13.7@59.081,43.211 ; J13.7@58.69,43.02 58.69,42.815 56.892,41.017 56.892,40.93 55.335,39.373 55.243,39.373 54.859,38.989 54.859,35.141 56.8,33.2 108.2,33.2 112,37 112,54 v1(116,58) 119,61 148,61 157,52 157,38.505 v1(146.918,28.423) 144.035,25.54 144.035,25.272 v1(143.988,25.225) ; v1(199.047,28.423) 199.074,28.396 202.964,28.396 204.559,26.801 204.584,26.801 204.932,26.453 R52.2@204.932,26.428
  Bottom Layer w0.254: v1(113,61) v1(116,58) ; v1(143.988,25.225) 146.503,25.225 150.722,21.006 R79.1@150.722,20.444 ; v1(146.918,28.423) v1(199.047,28.423)
AC_GD_RST/EN: J13.5 J14.5 R81.1 | length 308.5
  Top Layer w0.254: v1(55,40) 55,42.635 55.185,42.82 J13.5@56.15,42.82 ; v1(56,36) 58,34 108,34 111,37 111,55 v1(116,60) 118,62 148,62 158.199,51.801 158.199,38.658 153.305,33.764 153.217,33.764 v1(145.4,25.946) ; J14.5@56.05,146.18 56.05,144.95 57,144 64.125,144 65.125,145 87,145 110,122 110,66 v1(114,62)
  Bottom Layer w0.254: v1(55,40) 55,36.149 55.149,36 v1(56,36) ; v1(114,62) v1(116,60) ; v1(145.4,25.946) 146.653,25.946 152.155,20.444 R81.1@152.28,20.444
AC_KS1: J1.3 J1.4 MD1.KS1 R17.2 | length 10.4
  Top Layer w1: R17.2@71.3,88.6 71.87,88.03 71.87,86.73 MD1.KS1@72.1,86.5 ; MD1.KS1@72.425,86.5 73.425,85.5 J1.4@74.975,85.5 J1.3@80.025,85.5
AC_KS2: J7.3 J7.4 MD1.KS2 R26.2 | length 10.9
  Top Layer w1: J7.4@32.175,85.5 J7.3@37.225,85.5 38.775,85.5 39.775,86.5 40.1,86.5 40.33,86.73 40.33,88.13 R26.2@40.9,88.7
AC_KS3: J2.3 J2.4 MD1.KS3 R18.2 | length 10.8
  Top Layer w1: R18.2@71.3,100.3 71.87,100.87 71.87,101.946 71.925,102 72,102 72,102.075 73.29,103.365 74.89,103.365 J2.3@75.012,103.487 ; J2.3@75,103.5 J2.3@75.025,103.5 J2.4@80.075,103.5
AC_KS4: J8.3 J8.4 MD1.KS4 R27.2 | length 10.9
  Top Layer w1: J8.3@32.175,103.5 J8.4@37.225,103.5 37.36,103.365 38.91,103.365 39.775,102.5 40.1,102.5 40.33,102.27 40.33,100.87 R27.2@40.9,100.3
AC_PWM1: C37.2 R58.1 R91.2 U1.2 | length 60.7
  Top Layer w0.254: U1.2@91.006,20.484 90.958,20.436 90.958,18.603 90.392,18.037 C37.2@90.392,17.034 R91.2@88.546,17.034 88.546,17.009 89.501,16.054 89.501,14.394 91.636,12.26 101.87,12.26 112.38,22.77 v1(133.658,22.77)
  Bottom Layer w0.254: v1(133.658,22.77) 134.703,21.725 R58.1@134.703,20.444
AC_PWM2: C36.2 R60.1 R89.2 U1.5 | length 57.9
  Top Layer w0.254: U1.5@94.816,20.484 94.816,18.603 95.496,17.924 95.496,17.382 C36.2@95.844,17.034 R89.2@94.021,17.034 94.021,17.009 94.868,16.162 94.868,14.192 95.797,13.264 100.246,13.264 111.445,24.463 v1(133.758,24.463)
  Bottom Layer w0.254: v1(133.758,24.463) 136.303,21.918 R60.1@136.303,20.444
AC_PWM3: C38.2 R62.1 R92.2 U1.9 | length 53.3
  Top Layer w0.254: U1.9@96.086,25.884 96.086,28.34 C38.2@95.842,28.584 R92.2@97.489,28.584 97.489,28.609 98.339,29.459 98.339,31.774 98.565,32 102.148,32 108.148,26 v1(133.758,26)
  Bottom Layer w0.254: v1(133.758,26) 137.903,21.855 R62.1@137.903,20.444
AC_PWM4: C39.2 R65.1 R93.2 U1.12 | length 60.7
  Top Layer w0.254: R93.2@90.392,28.609 C39.2@92.176,28.609 ; U1.12@92.276,25.884 92.276,28.509 C39.2@92.176,28.609 ; v1(133.859,27.315) 110.48,27.315 105.222,32.573 93.723,32.573 93.001,31.851 93.001,29.459 92.176,28.634 C39.2@92.176,28.609
  Bottom Layer w0.254: v1(133.859,27.315) 139.503,21.67 R65.1@139.503,20.444
CLK_MOD_AC: R101.1 R169.2 U9.7 U10.7 | length 188.9
  Top Layer w0.254: U9.7@18.235,43.75 R169.2@18.235,37.321 18.306,37.25 24.75,37.25 ; 24.75,37.321 26.786,37.321 26.935,37.47 U10.7@26.935,43.75 ; 24.8,37.3 24.75,37.25 ; v1(159,4) 159,3.329 157.771,2.1 124.213,2.1 123.525,2.788 36.964,2.788 24.75,15.002 24.75,37.25
  Bottom Layer w0.254: v1(159,4) 159.693,4 160.239,3.454 161.254,3.454 161.522,3.722 R101.1@161.522,5.144
CLK_MOD_DC: R106.1 R154.2 U6.7 U7.7 | length 167.5
  Top Layer w0.254: R154.2@131.766,125.743 132.001,125.978 132.001,126.949 ; U6.7@132.001,133.863 132.001,126.949 ; U7.7@148.536,134.013 148.536,127.876 147.6,126.94 ; v1(165.326,4.419) 167.319,4.419 169,6.1 169,13.76 170.4,15.16 170.4,23.619 169.206,24.812 169.206,25.1 169,25.306 169,48.008 147.6,69.408 147.6,126.94 ; 132.001,126.949 147.591,126.949 147.6,126.94
  Bottom Layer w0.254: R106.1@164.822,5.144 164.947,5.144 165.145,4.946 165.145,4.667 165.326,4.486 v1(165.326,4.419)
DATA_I_AC: C97.1 R95.1 R168.2 | length 192.4
  Top Layer w0.254: R168.2@17,39.4 16.9,39.3 16.9,19.216 34.873,1.243 157.556,1.243 159.9,3.587 159.9,8.075 161.04,9.214 161.04,20.703 v1(161.63,21.294) C97.1@161.63,22.77
  Bottom Layer w0.254: R95.1@161.63,20.444 v1(161.63,21.294)
DATA_I_DC: C78.1 R100.1 R153.2 | length 136.2
  Top Layer w0.254: R153.2@130.731,129.591 130.731,129.566 130.383,129.218 130.358,129.218 129,127.86 129,125.995 130.493,124.503 145.497,124.503 146,124 146,68.642 153.09,61.552 153.09,61.495 167,47.584 167,32.213 163.787,29 163.787,23.594 164.77,22.61 164.697,22.537 v1(164.697,21.294)
  Bottom Layer w0.254: v1(164.697,21.294) 164.697,20.494 R100.1@164.747,20.444
DATA_V_AC: C106.1 R96.1 R178.2 | length 164.4
  Top Layer w0.254: v1(25.665,38.071) R178.2@25.665,39.421 ; v1@25.7,36.195 25.7,17.3 37.8,5.2 112.483,5.2 113.07,5.787 125.547,5.787 128.534,2.8 157.23,2.8 158,3.57 v1(158,4) 158,5.143 C106.1@158.247,5.39
  Bottom Layer w0.254: v1(25.665,36.23) v1(25.665,38.071) ; v1(158,4) 158,4.016 158.422,4.438 R96.1@158.422,5.144
DATA_V_DC: C87.1 R105.1 R163.2 | length 119.9
  Top Layer w0.254: v1(146,126) 146.8,125.2 146.8,69.04 168,47.84 168,31.571 167.061,30.632 167.061,23.55 167.863,22.748 v1(167.863,21.294) ; v1(147,128) 147,128.067 147.266,128.332 R163.2@147.266,130.007
  Bottom Layer w0.254: v1(146,126) 146,127 v1(147,128) ; R105.1@167.863,20.444 v1(167.863,21.294)
DC_BUF_PMW1: J15.2 R111.2 | length 159.5
  Top Layer w0.254: R111.2@145.67,50.875 145.702,50.906 v1(145.702,52.174) ; v1(148.455,69.675) 148.455,124.755 153.4,129.7 153.4,136.4 173,156 204.9,156 205.53,155.37 208.93,155.37 210.53,153.77 J15.2@210.53,151.62
  Bottom Layer w0.254: v1(145.702,52.174) 150.4,56.872 150.4,69.146 149.871,69.675 v1(148.455,69.675)
DC_BUF_PMW2: J15.4 R112.2 | length 155
  Top Layer w0.254: R112.2@140.516,50.875 v1(140.516,52.174) ; v1(149.3,68.8) 149.3,124.2 154.3,129.2 154.3,135.9 173.4,155 202.6,155 202.99,154.61 207.09,154.61 207.99,153.71 J15.4@207.99,151.62
  Bottom Layer w0.254: v1(140.516,52.174) 149.265,60.923 149.265,68.765 v1(149.3,68.8)
DC_BUF_PMW3: J16.2 R114.2 | length 64.4
  Top Layer w0.254: v1(140.347,34.038) 140.347,35.223 R114.2@140.399,35.275 ; v1(192,37) 198.067,37 198.447,37.38 J16.2@200.47,37.38
  Bottom Layer w0.254: v1(140.347,34.038) 145.309,39 190,39 v1(192,37)
DC_BUF_PMW4: J16.4 R117.2 | length 63.1
  Top Layer w0.254: v1(145.553,34.038) R117.2@145.553,35.275 ; v1(190,36) 202.846,36 203.01,36.164 J16.4@203.01,37.38
  Bottom Layer w0.254: v1(145.553,34.038) 146.39,33.2 155.157,33.2 159.957,38 188,38 v1(190,36)
DC_BUS_DAB: C19.1 C20.1 C21.1 C75.2 C76.2 C79.1 C80.1 C84.2 C85.2 C86.1 C89.1 C91.2 C190.1 C191.1 C192.1 C193.1 C194.1 C195.1 C196.1 C197.1 C198.1 C199.1 J25.1 J25.2 J25.3 J25.4 J25.5 J25.6 MD2.DC1- MD2.DC2- R40.1 R41.1 R164.1 TP18.1 U6.4 U7.3 U7.4 U8.12 U8.13 U8.14 U8.15 U8.16 | length 43
  Top Layer w0.254: C80.1@128.366,151.513 128.401,151.548 128.401,152.401 v1(129,153) ; U6.4@129.461,144.763 129.48,144.783 129.48,146.18 v1(129.5,146.2) ; C79.1@134.749,151.513 134.953,151.717 134.953,152.953 v1(135,153) ; v1(135,149) 134.988,148.988 134.988,148.556 134.72,148.288 C75.2@134.655,148.288 136.671,148.288 C76.2@136.816,148.433 136.816,149.749 137,149.933 v1(137,150) ; v1(145,164) 146.527,162.473 R164.1@146.527,149.343 146.189,149.005 v1(145.236,149.005) ; U7.4@145.996,144.913 145.998,144.915 145.998,146.998 v1(146,147) ; v1(146,148) 146.047,147.953 146.571,147.953 147.211,147.313 C86.1@147.236,147.313 ; R164.1@146.552,149.343 147.236,148.66 C86.1@147.236,147.313 ; U7.3@147.266,144.913 147.251,144.928 147.251,147.298 C86.1@147.236,147.313 ; v1@151.577,150.461 v1(151.577,150.527) 151.577,149.357 C85.2@151.582,149.353 ; C84.2@151.66,147.351 151.66,146.406 152,146.067 v1(152,146)
  Top Layer w0.5: R40.1@206.35,169.3 206.35,169.308 R40.1@206.592,169.55
  Top Layer w1: C20.1@206.35,164 R40.1@206.35,169.3
  other v1: 180,54 181,54 180,55 181,55 180,56 181,56 180,57 181,57 180,58 181,58 138.7,145.7 138.7,146.367 138.7,147.104 157,162 158,162 159,162 160,162 161,162 157,163 158,163 159,163 138,164 139,164 140,164 141,164 142,164 143,164 144,164 157,164 158,164 138,165 139,165 140,165 141,165 142,165 143,165 144,165 145,165 157,165 158,165 159,165 138,166 139,166 140,166 141,166 142,166 143,166 144,166 145,166 157,166 158,166 159,166 160,166 161,166 138,167 139,167 140,167 141,167 142,167 143,167 144,167 145,167 157,167 158,167 159,167 160,167 161,167 138,168 139,168 140,168 141,168 142,168 143,168 144,168 145,168 157,168 158,168 159,168 160,168 161,168 138,169 139,169 140,169 141,169 142,169 143,169 144,169 145,169 157,169 158,169 159,169 160,169 161,169 138,170 139,170 140,170 141,170 142,170 143,170 144,170 145,170 157,170 158,170 159,170 160,170 161,170 138,171 139,171 140,171 141,171 142,171 143,171 144,171 145,171 157,171 158,171 159,171 160,171 161,171 138,172 139,172 140,172 141,172 142,172 143,172 144,172 145,172 157,172 158,172 159,172 160,172 161,172 138,173 139,173 140,173 141,173 142,173 143,173 144,173 145,173 157,173 158,173 159,173 160,173 161,173 138,174 139,174 140,174 141,174 142,174 143,174 144,174 145,174 157,174 158,174 159,174 160,174 161,174 138,175 139,175 140,175 141,175 142,175 143,175 144,175 145,175 157,175 158,175 159,175 160,175 161,175 157,176 158,176 159,176 160,176 161,176 157,177 158,177 159,177 160,177 161,177
DC_BUS_NEG: C2.1 C14.1 C16.1 C17.1 C18.1 C26.1 C165.1 C168.1 C185.1 C186.1 C187.1 C188.1 C189.1 MD1.DC1- MD1.DC2- R39.1 R41.2 TP17.1 | length 5.3
  Top Layer w0.5: R39.1@32.54,169.55 32.595,169.495 R39.1@32.595,169.3
  Top Layer w1: R39.1@32.595,169.3 32.595,164.305 C18.1@32.65,164.25
  other v1: 82,55 83,55 82,56 83,56 82,57 83,57 82,58 83,58 82,59 83,59 127,164 128,164 129,164 130,164 127,165 128,165 129,165 130,165 123,166 124,166 125,166 126,166 127,166 128,166 129,166 130,166 123,167 124,167 125,167 126,167 127,167 128,167 129,167 130,167 123,168 124,168 125,168 126,168 127,168 128,168 129,168 130,168 123,169 124,169 125,169 126,169 127,169 128,169 129,169 130,169 123,170 124,170 125,170 126,170 127,170 128,170 129,170 130,170 123,171 124,171 125,171 126,171 127,171 128,171 129,171 130,171 123,172 124,172 125,172 126,172 127,172 128,172 129,172 130,172 123,173 124,173 125,173 126,173 127,173 128,173 129,173 130,173 123,174 124,174 125,174 126,174 127,174 128,174 129,174 130,174 123,175 124,175 125,175 126,175 127,175 128,175 129,175 130,175
DC_BUS_POS: C1.2 C3.2 C4.2 C5.2 C6.2 C7.2 C8.2 C9.2 C11.2 C12.2 C13.2 C15.2 C23.2 C24.2 C25.2 C65.2 C71.2 C161.2 C163.2 C164.2 C166.2 C167.2 C181.2 C182.2 C183.2 C184.2 D1.1 D2.1 D3.1 D4.1 J24.1 J24.2 J24.3 J24.4 J24.5 J24.6 MD1.DC1+ MD1.DC2+ MD2.DC1+ MD2.DC2+ R1.2 R3.2 R155.1 TP13.1 TP14.1 | length 52.2
  Top Layer w0.254: R155.1@152.5,261.2 152.5,267.9 160,275.4 C5.2@160,276
  Top Layer w0.5: R1.2@32.54,268.2 32.595,268.255 R1.2@32.595,268.45 ; MD1.DC1+@72,74 MD1.DC1+@72.2,73.8 ; R3.2@206.471,270.5 206.471,270.371 R3.2@206.592,270.25
  Top Layer w1: R1.2@32.595,268.45 32.595,275.695 C7.2@32.65,275.75 ; MD1.DC2+@71.9,115.2 71.938,115.162 76.962,115.162 D2.1@77.1,115.023 ; MD1.DC1+@72.1,73.7 72.2,73.8 72.25,73.85 77.05,73.85 D1.1@77.2,74 ; D3.1@184.4,115 184.55,115.15 189.35,115.15 MD2.DC1+@189.5,115.3 MD2.DC1+@189.6,115.4 ; D4.1@184.5,73.977 184.638,73.838 189.362,73.838 MD2.DC2+@189.4,73.8 ; C4.2@206.35,275.75 206.471,275.629 R3.2@206.471,270.5
  other v1: 11,134 12,134 11,135 12,135 11,136 12,136 11,137 12,137 11,138 12,138 11,139 12,139 11,140 12,140 11,141 12,141 11,142 12,142 11,143 12,143 118,143 119,143 11,144 12,144 118,144 119,144 253,144 254,144 255,144 118,145 119,145 253,145 254,145 255,145 118,146 119,146 253,146 254,146 255,146 118,147 119,147 254,147 255,147 118,148 119,148 255,148 118,149 119,149
DC_DS1: D11.2 J3.1 J3.2 | length 10.6
  Top Layer w1: D11.2@176.5,102 177.54,100.96 J3.1@181.575,100.96 J3.2@186.625,100.96
DC_DS2: D23.2 J9.1 J9.2 | length 11.4
  Top Layer w1: J9.1@224.375,100.96 J9.2@229.425,100.96 233.16,100.96 234,101.8 234,102.9 D23.2@234.2,103.1
DC_DS3: D12.2 J4.1 J4.2 | length 11.2
  Top Layer w1: D12.2@177,85.84 177.5,86.34 177.5,87.4 178.14,88.04 J4.2@181.575,88.04 186.54,88.04 J4.1@186.6,88.1
DC_DS4: D24.2 J10.1 J10.2 | length 11.7
  Top Layer w1: J10.2@224.375,88.04 J10.1@229.425,88.04 234.014,88.04 234.014,86.714 234.428,86.3 D24.2@234.6,86.3
DC_FAULT_FET1: J15.6 R57.2 | length 198.2
  Top Layer w0.254: R57.2@147.033,10.994 147.033,12.033 151,16 151,26.019 163.04,38.059 v1(163.04,50.627) ; v1(154.226,64.058) 150.4,67.883 150.4,124.1 155,128.7 155,134.8 174.2,154 205,154 205.5,153.5 205.5,151.67 J15.6@205.45,151.62
  Bottom Layer w0.254: v1(154.226,64.058) 154.226,59.415 163.013,50.627 v1(163.04,50.627)
DC_FAULT_FET2: J15.8 R68.2 | length 193
  Top Layer w0.254: R68.2@148.647,10.994 148.923,11.271 148.923,11.723 151.923,14.723 151.923,25.565 164,37.642 164,49.038 163.829,49.208 v1(163.829,49.275) ; v1@154.5,65.5 151.4,68.6 151.4,123.7 156.2,128.5 156.2,134.6 174.9,153.3 202.4,153.3 202.91,152.79 J15.8@202.91,151.62
  Bottom Layer w0.254: v1(154.455,65.475) 155,64.93 155,60 163.829,51.171 v1(163.829,49.275)
DC_FAULT_FET3: J16.6 R78.2 | length 75.9
  Top Layer w0.254: R78.2@150.37,10.994 152.758,13.383 152.758,25.315 164.612,37.168 v1@165.333,37.168 ; v1(173.18,37.062) 173.207,37.035 173.537,37.035 175.573,35 204.849,35 205.55,35.701 J16.6@205.55,37.38
  Bottom Layer w0.254: v1(165.35,37.185) 165.375,37.21 172.965,37.21 173.113,37.062 v1(173.18,37.062)
DC_FAULT_FET4: J16.8 R86.2 | length 77.6
  Top Layer w0.254: R86.2@151.97,10.994 153.517,12.541 153.517,25.031 164.647,36.161 v1(165.35,36.161) ; v1(173.207,36.1) 175.307,34 206,34 208.09,36.09 208.09,37.38 J16.8@207.582,36.872
  Bottom Layer w0.254: v1(165.35,36.161) 165.381,36.131 173.176,36.131 v1(173.207,36.1)
DC_G1: J3.5 J3.6 MD2.G1 R19.2 | length 15.3
  Top Layer w1: J3.5@181.575,106.04 J3.6@186.625,106.04 189.16,106.04 MD2.G1@192.7,102.5 ; R19.2@191.9,100.3 192.47,100.87 192.47,102.27 MD2.G1@192.7,102.5 ; MD2.G1@192.8,102.6 MD2.G1@192.7,102.5
DC_G2: J9.5 J9.6 MD2.G2 R29.2 | length 16
  Top Layer w1: MD2.G2@218.4,102.5 218.53,102.37 218.53,100.87 R29.2@219.1,100.3 ; MD2.G2@218.53,102.53 218.53,104.53 220.04,106.04 J9.5@224.375,106.04 J9.6@229.425,106.04
DC_G3: J4.5 J4.6 MD2.G3 R20.2 | length 16.6
  Top Layer w1: J4.6@181.575,82.96 J4.5@186.625,82.96 191.96,82.96 192.8,83.8 MD2.G3@192.8,86.5 ; R20.2@191.8,88.5 191.8,87.725 192.7,86.825 MD2.G3@192.7,86.5
DC_G4: J10.5 J10.6 MD2.G4 R30.2 | length 15
  Top Layer w1: R30.2@219.1,88.7 219.1,87.625 218.3,86.825 MD2.G4@218.3,86.5 221.73,83.07 J10.6@224.23,83.07 ; J10.6@224.375,82.96 J10.5@229.425,82.96 229.46,82.96 J10.5@229.5,83
DC_GD_RDY: J15.7 J16.7 R50.2 R82.1 | length 312.2
  Top Layer w0.254: v1(153,68) 152.5,68.5 152.5,123.4 156.9,127.8 156.9,133.9 172,149 193,149 197.3,144.7 202.4,144.7 202.8,145.1 202.8,146.07 J15.7@202.91,146.18 ; v1(171.927,25.75) 179.177,33 208,33 210.637,35.637 211.637,35.637 v1(213,37) 213,31.354 213.354,31 v1(227,31) ; v1(206.697,42.338) 206.707,42.348 207.582,42.348 208.09,42.856 J16.7@208.09,43.02 ; R50.2@209.753,26.144 209.753,26.169 212.095,28.511 v1(225.767,28.511)
  Bottom Layer w0.254: v1(153,68) 153,59 169,43 202.728,43 203.202,42.527 205.742,42.527 205.889,42.379 206.657,42.379 v1(206.697,42.338) 206.741,42.382 210.966,42.382 213,40.348 v1(213,37) ; R82.1@153.839,20.444 153.839,22.759 156.829,25.75 v1(171.927,25.75) ; v1(225.767,28.511) 227,29.744 v1(227,31)
DC_GD_RST/EN: J15.5 J16.5 R83.1 | length 275.4
  Top Layer w0.254: v1(153.385,69.015) 153.385,122.685 158.3,127.6 158.3,134 171.3,147 192,147 194.815,144.185 205.301,144.185 205.45,144.334 J15.5@205.45,146.18 ; v1(173.362,25.75) 179.861,32.25 209.25,32.25 v1(212,35) ; v1(204.137,40.317) 204.137,42.137 204.683,42.683 205.213,42.683 J16.5@205.55,43.02
  Bottom Layer w0.254: v1(153.385,69.015) 152.195,69.015 151.2,68.02 151.2,58.8 168,42 196.152,42 200.508,37.644 204.137,37.644 ; R83.1@155.397,20.444 155.397,22.783 157.714,25.1 172.712,25.1 v1(173.362,25.75) ; v1(204.137,40.317) 204.137,37.644 ; v1(212,35) 206.781,35 204.137,37.644
DC_KS1: J3.3 J3.4 MD2.KS1 R19.1 | length 10.6
  Top Layer w1: J3.3@181.575,103.5 J3.4@186.625,103.5 188.175,103.5 MD2.KS1@188.975,102.7 ; MD2.KS1@189.4,102.8 189.73,102.47 189.73,100.87 R19.1@190.3,100.3
DC_KS2: J9.3 J9.4 MD2.KS2 R29.1 | length 10.6
  Top Layer w1: R29.1@220.7,100.3 221.27,100.87 221.27,101.946 221.625,102.3 MD2.KS2@221.7,102.3 ; MD2.KS2@221.825,102.5 222.725,103.4 J9.3@224.375,103.4 ; J9.3@224.375,103.5 J9.4@229.425,103.5 229.5,103.5 J9.4@229.6,103.6
DC_KS3: J4.3 J4.4 MD2.KS3 R20.1 | length 9.8
  Top Layer w1: J4.4@181.575,85.5 J4.3@186.3,85.5 ; J4.3@186.625,85.5 186.76,85.635 188.31,85.635 MD2.KS3@189.175,86.5 ; MD2.KS3@189.5,86.5 189.5,86.825 190.3,87.625 R20.1@190.3,88.3
DC_KS4: J10.3 J10.4 MD2.KS4 R30.1 | length 10.9
  Top Layer w1: R30.1@220.7,88.7 220.7,87.625 221.5,86.825 MD2.KS4@221.5,86.5 221.825,86.5 222.825,85.5 J10.3@229.5,85.5
DC_OC: R94.2 U25.7 | length 163.1
  Top Layer w0.254: R94.2@153.839,10.969 154,11.131 154,24.287 158.999,29.285 v1(159.636,29.285) ; v1(276,55) 276,61.21 277.135,62.345 U25.7@277.135,67.247
  Bottom Layer w0.254: v1(159.636,29.285) 164.566,29.285 165.28,30 223,30 235.373,42.373 235.373,43.26 235.74,43.627 236.627,43.627 239,46 269.965,46 276,52.035 v1(276,55)
DC_OC_CMP: C116.1 R109.2 R183.2 | length 123
  Top Layer w0.254: R109.2@155.572,10.969 155.572,23.872 162.424,30.724 v1(162.424,31.319) ; v1(251.706,48.83) 253.017,48.83 253.017,48.953 R183.2@254.83,48.953
  Bottom Layer w0.254: v1(162.424,31.319) 164.105,33 220,33 235,48 250.876,48 v1(251.706,48.83)
DC_PWM1: C50.2 R59.2 R121.2 U2.2 | length 73.8
  Top Layer w0.254: v1(134.901,4.419) 137,6.518 137,52.245 139.638,54.883 147.617,54.883 150.432,52.068 150.432,50.627 149.105,49.3 R121.2@149.105,49.275 C50.2@147.387,49.275 147.387,49.25 146.972,48.835 U2.2@146.972,45.775
  Bottom Layer w0.254: R59.2@134.89,5.095 134.89,4.43 v1(134.901,4.419)
DC_PWM2: C49.2 R61.2 R120.2 U2.5 | length 66.5
  Top Layer w0.254: v1(136.524,4.419) 137.662,5.557 137.662,24.955 138,25.293 138,51.765 138.704,52.469 ; 138.714,52.459 139.924,53.668 144.679,53.668 144.828,53.52 144.828,50.177 143.951,49.3 R120.2@143.951,49.275 C49.2@142.233,49.275 142.233,47.179 143.162,46.25 U2.5@143.162,45.775
  Bottom Layer w0.254: R61.2@136.503,5.095 136.524,5.074 v1(136.524,4.419)
DC_PWM3: C51.2 R63.2 R122.2 U2.9 | length 42
  Top Layer w0.254: v1(138.116,4.419) 138.116,24.767 144.751,31.402 144.751,36.726 144.602,36.875 R122.2@143.835,36.875 C51.2@142.117,36.875 142.117,39.675 141.892,39.9 U2.9@141.892,40.375
  Bottom Layer w0.254: v1(138.116,4.419) R63.2@138.116,5.095
DC_PWM4: C52.2 R66.2 R123.2 U2.12 | length 44.3
  Top Layer w0.254: v1(139.728,4.419) 139.728,23.306 150.111,33.688 150.111,36.609 149.845,36.875 R123.2@148.989,36.875 C52.2@147.271,36.875 147.271,38.331 145.702,39.9 U2.12@145.702,40.375
  Bottom Layer w0.254: v1(139.728,4.419) R66.2@139.728,5.095
DEBUG_GPIO1: J19.5 R126.1 | length 4
  Bottom Layer w0.254: J19.5@202.27,2 202.272,2.002 202.272,3.494 203.972,5.194 R126.1@204.097,5.194
DEBUG_GPIO2: J19.4 R128.1 | length 3.6
  Bottom Layer w0.254: J19.4@204.81,2 204.812,2.002 204.812,4.634 205.372,5.194 R128.1@205.497,5.194
DEBUG_GPIO3: J19.3 R130.1 | length 3.5
  Bottom Layer w0.254: R130.1@206.897,5.194 207.022,5.194 207.352,4.864 207.352,2.002 J19.3@207.35,2
DEBUG_GPIO4: J19.2 R132.1 | length 3.9
  Bottom Layer w0.254: R132.1@208.297,5.194 208.422,5.194 209.892,3.724 209.892,2.002 J19.2@209.89,2
EF_dVdt: C61.1 U3.7 | length 2.7
  Top Layer w0.254: U3.7@74.4,14.814 74.406,14.814 74.46,14.76 C61.1@74.46,12.161
EF_EN: R134.1 R138.2 U3.1 | length 6.6
  Top Layer w0.254: 75.96,16.424 75.96,20.468 76.195,20.703 R134.1@78.414,20.703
